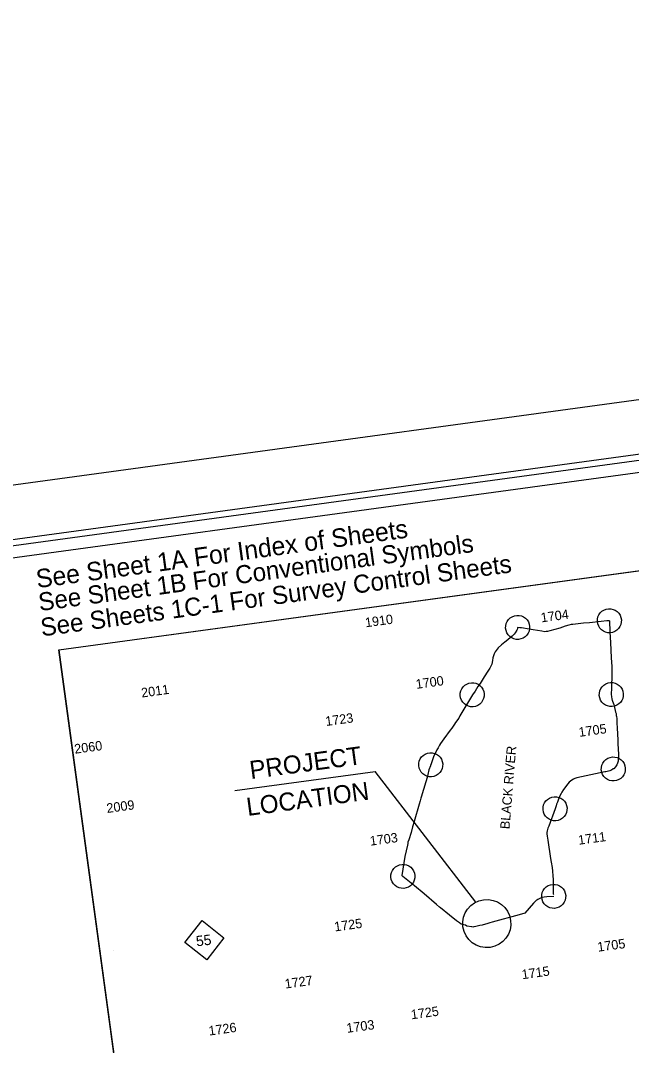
# Model space of a CAD drawing. Extents: x 2110583 to 2112764, y 580993 to 582575.
# Drawn here: x 2110891 to 2111195, y 582064 to 582575 of the extents above; entities that cross this region are included whole.
import ezdxf

# ---------------------------------------------------------------- set-up
doc = ezdxf.new("R2010")
doc.units = 0
for name, color, linetype in [('Default', 7, 'Continuous'), ('Prop DSN Text', 7, 'Continuous'), ('Scratch_Level_0', 7, 'Continuous'), ('Sheet Data Field CELL', 7, 'Continuous'), ('Sheet Plot Border Inside CELL', 7, 'Continuous'), ('Sheet Plot Border Outside CELL', 7, 'Continuous'), ('Sheet Title CELL', 7, 'Continuous')]:
    doc.layers.add(name, color=color, linetype=linetype)

msp = doc.modelspace()

# ---------------------------------------------------------------- linework, layer by layer
at = {"layer": 'Default'}
msp.add_line((2110936.95, 582111.14), (2110936.96, 582111.09), dxfattribs=at)
msp.add_lwpolyline([(2110972.71, 582114.94), (2110981.3, 582125.83), (2110992.19, 582117.24), (2110983.6, 582106.35)], close=True, dxfattribs=at)
at = {"layer": 'Prop DSN Text'}
for p in [(2110997.69, 582190.7), (2111117.86, 582135.05)]:
    msp.add_line(p, (2111067.61, 582200.13), dxfattribs=at)
for points in [[(2111138.67, 582272.05), (2111138.55, 582271.29), (2111138.34, 582270.7), (2111137.42, 582269.28), (2111136.98, 582268.68), (2111136.42, 582268.13), (2111135.98, 582267.64), (2111132.92, 582265.24)], [(2111184.43, 582275.37), (2111183.07, 582275.26), (2111180.3, 582275.01), (2111174.54, 582274.32), (2111171.51, 582274.1), (2111166.26, 582273.58), (2111165.4, 582273.46), (2111164.21, 582273.17), (2111162.44, 582272.64), (2111159.75, 582271.72), (2111154.74, 582270.39), (2111153.5, 582270.03), (2111152.96, 582269.95), (2111152.29, 582269.92), (2111150.77, 582270.13), (2111146.37, 582270.82), (2111144.44, 582271.2), (2111140.62, 582271.83), (2111139.73, 582271.91), (2111138.67, 582272.05)], [(2111184.43, 582275.37), (2111184.5, 582274.01), (2111184.61, 582271.1), (2111184.73, 582269.65), (2111185.05, 582264.6), (2111185.36, 582256.8), (2111185.68, 582252.63)], [(2111132.92, 582265.24), (2111132.27, 582264.74), (2111131.53, 582264.07), (2111130.63, 582263.35), (2111129.03, 582261.89), (2111128.43, 582261.27), (2111127.5, 582259.86), (2111126.99, 582258.84), (2111126.6, 582257.85), (2111126.29, 582256.84), (2111126.09, 582255.63), (2111125.72, 582253.77), (2111125.47, 582253.06), (2111124.81, 582251.8), (2111123.76, 582250.25), (2111122.01, 582247.38), (2111119.97, 582244.15), (2111118.89, 582242.5), (2111117.44, 582240.19), (2111116.24, 582238.4), (2111109.83, 582228.03), (2111109.34, 582226.8)], [(2111185.68, 582252.63), (2111185.62, 582249.88), (2111185.57, 582248.66), (2111185.43, 582241.91), (2111185.39, 582238.57), (2111185.44, 582237.62), (2111185.48, 582237.26), (2111185.6, 582236.64), (2111185.68, 582236.26), (2111185.77, 582235.98), (2111185.83, 582235.8), (2111186, 582235.26), (2111186.35, 582234.39), (2111186.57, 582233.62)], [(2111186.57, 582233.62), (2111186.78, 582232.92), (2111187.55, 582229.76), (2111187.73, 582229.15), (2111187.83, 582228.52), (2111187.89, 582228.16), (2111187.96, 582227.63), (2111188.06, 582226.6), (2111188.09, 582225.62), (2111188.19, 582224.43), (2111188.24, 582221.82)], [(2111109.34, 582226.8), (2111107.69, 582224.57), (2111107.26, 582223.86), (2111106.86, 582223.35), (2111105.86, 582221.88), (2111104.99, 582220.87), (2111101.85, 582216.46), (2111100.12, 582214.1), (2111099.64, 582213.32), (2111098.96, 582211.99), (2111098.34, 582211.07), (2111096.79, 582207.48), (2111095.32, 582203.53)], [(2111188.36, 582220.58), (2111188.39, 582220.29), (2111188.64, 582214.55), (2111188.83, 582211), (2111188.89, 582209.11), (2111188.91, 582206.93), (2111188.85, 582206.05), (2111188.74, 582205.28), (2111188.53, 582204.4), (2111188.16, 582203.54), (2111187.84, 582203), (2111187.46, 582202.44), (2111186.62, 582201.59), (2111186.39, 582201.46)], [(2111188.24, 582221.82), (2111188.24, 582221.68), (2111188.36, 582220.58)], [(2111095.32, 582203.53), (2111095.29, 582203.45), (2111095.14, 582202.95), (2111094.39, 582201.02), (2111093.82, 582198.73), (2111093.56, 582197.15)], [(2111182.09, 582199.98), (2111168.15, 582197.1), (2111167.19, 582196.75), (2111166.86, 582196.61), (2111166.51, 582196.41), (2111165.68, 582195.9), (2111165.08, 582195.44), (2111164.36, 582194.81), (2111163.73, 582194.08), (2111161.57, 582191.2), (2111160.72, 582189.9), (2111160.35, 582189.26), (2111159.35, 582187.31), (2111158.51, 582184.87), (2111158.12, 582183.86), (2111157.87, 582183.12)], [(2111186.39, 582201.46), (2111185.42, 582200.8), (2111185.04, 582200.61), (2111184.62, 582200.48), (2111182.59, 582200.08), (2111182.48, 582200.06), (2111182.09, 582199.98)], [(2111093.56, 582197.15), (2111092.94, 582195.05), (2111090.64, 582187.42), (2111090.46, 582186.82), (2111090.12, 582185.54), (2111089.61, 582183.91), (2111087.13, 582175.22)], [(2111157.47, 582182.04), (2111157.31, 582181.6), (2111154.16, 582172.96), (2111153.78, 582171.86), (2111153.4, 582170.59), (2111153.25, 582169.74), (2111153.28, 582168.76), (2111153.33, 582168.36), (2111153.42, 582167.96), (2111153.73, 582165.98), (2111155.13, 582156.86)], [(2111157.87, 582183.12), (2111157.83, 582183.02), (2111157.47, 582182.04)], [(2111087.13, 582175.22), (2111086.26, 582172.54), (2111085.49, 582169.83), (2111084.34, 582166.12), (2111083.97, 582164.89), (2111083.93, 582164.26), (2111083.77, 582163.53), (2111082.41, 582157.86), (2111080.89, 582148.26)], [(2111155.13, 582156.86), (2111155.47, 582155.02), (2111155.88, 582152.32), (2111156.12, 582150.43), (2111156.28, 582148.18), (2111156.31, 582146.37), (2111156.32, 582143.6)], [(2111120.99, 582123.63), (2111119.8, 582123.31), (2111117.9, 582122.9), (2111116.88, 582122.7), (2111116.32, 582122.63), (2111115.78, 582122.69), (2111113.41, 582123.14), (2111112.59, 582123.59), (2111111.79, 582123.75), (2111110.52, 582124.12), (2111109.63, 582124.75), (2111108.12, 582125.73), (2111104.61, 582128.56), (2111100.2, 582132.14), (2111099.65, 582132.56), (2111098.26, 582133.85), (2111092.01, 582139.26), (2111087.31, 582143.11), (2111081.43, 582147.88), (2111080.89, 582148.26)], [(2111156.32, 582143.6), (2111156.32, 582143.29), (2111156.36, 582140.63), (2111156.43, 582139.15), (2111156.48, 582138.92)], [(2111156.65, 582137.93), (2111153.23, 582137.69), (2111151.86, 582137.54), (2111151.13, 582137.39), (2111150.36, 582137.14), (2111149.79, 582136.93), (2111149.44, 582136.77), (2111148.7, 582136.35), (2111148.28, 582136.1), (2111147.89, 582135.79), (2111147.55, 582135.49), (2111147.22, 582135.16), (2111146.61, 582134.46), (2111142.18, 582129.58)], [(2111142.18, 582129.58), (2111139.36, 582128.72), (2111125.97, 582125.05)], [(2111125.97, 582125.05), (2111124.83, 582124.69), (2111124.34, 582124.54), (2111123.86, 582124.42), (2111120.99, 582123.63)]]:
    msp.add_lwpolyline(points, dxfattribs=at)
for centre, major_axis in [((2111184.43, 582275.37), (-1.61, 5.78)), ((2111138.67, 582272.05), (-1.61, 5.78)), ((2111116, 582238.47), (-1.61, 5.78)), ((2111185.39, 582238.57), (-1.61, 5.78)), ((2111095.32, 582203.53), (-1.61, 5.78)), ((2111186.39, 582201.46), (-1.61, 5.78)), ((2111157.31, 582181.6), (-1.61, 5.78)), ((2111081.43, 582147.88), (-1.61, 5.78)), ((2111156.65, 582137.93), (-1.61, 5.78)), ((2111123.29, 582124.34), (1.62, -11.9))]:
    msp.add_ellipse(centre, major_axis=major_axis, ratio=0.999692, dxfattribs=at)
at = {"layer": 'Scratch_Level_0'}
msp.add_lwpolyline([(2110909.81, 582260.89), (2111242.78, 582306.33), (2111281.74, 582020.84), (2110948.77, 581975.4)], close=True, dxfattribs=at)
at = {"layer": 'Sheet Plot Border Inside CELL'}
msp.add_lwpolyline([(2110773, 581021.72), (2112754.79, 581292.17), (2112583.51, 582547.28), (2110601.71, 582276.83)], close=True, dxfattribs=at)
at = {"layer": 'Sheet Plot Border Outside CELL'}
msp.add_lwpolyline([(2112585.22, 582574.72), (2110582.61, 582301.43), (2110761.18, 580992.92), (2112763.78, 581266.21)], close=True, dxfattribs=at)
at = {"layer": 'Sheet Title CELL'}
for q in [(2111242.78, 582306.33), (2110956.89, 581915.92)]:
    msp.add_line((2110909.81, 582260.89), q, dxfattribs=at)
for points in [[(2112557.18, 582540.6), (2110797.14, 582300.43)], [(2112552.03, 582533.84), (2110863.39, 582303.39)]]:
    msp.add_lwpolyline(points, dxfattribs=at)

# ---------------------------------------------------------------- texts
at = {"layer": 'Default'}
for s, height, rotation, p in [('1910', 4.705, 7.771, (2111062.9, 582272.08)), ('1704', 4.705, 7.771, (2111150.53, 582274.54)), ('1700', 4.705, 7.771, (2111088.18, 582241.39)), ('2011', 4.705, 7.771, (2110951.26, 582237.06)), ('1723', 4.705, 7.771, (2111043.1, 582222.87)), ('1705', 4.705, 7.771, (2111169.42, 582217.45)), ('2060', 4.705, 7.771, (2110917.9, 582209.03)), ('BLACK RIVER', 4.7046, 85.2808, (2111134.59, 582171.29)), ('2009', 4.705, 7.771, (2110933.96, 582179.49)), ('1703', 4.705, 7.771, (2111065.28, 582163.16)), ('1711', 4.705, 7.771, (2111169.13, 582163.63)), ('1725', 4.705, 7.771, (2111047.54, 582120.4)), ('55', 5.153, 6.7335, (2110978.57, 582112.97)), ('1705', 4.705, 7.771, (2111178.77, 582110.29)), ('1705', 4.705, 7.771, (2111178.77, 582110.29)), ('1715', 4.705, 7.771, (2111141, 582096.58)), ('1727', 4.705, 7.771, (2111022.84, 582091.93)), ('1725', 4.705, 7.771, (2111085.75, 582076.58)), ('1726', 4.705, 7.771, (2110984.87, 582068.48)), ('1703', 4.705, 7.771, (2111053.63, 582069.83))]:
    msp.add_text(s, height=height, rotation=rotation, dxfattribs=at).set_placement(p)
at = {"layer": 'Sheet Data Field CELL'}
for s, p in [('PROJECT', (2111005.62, 582196.38)), ('LOCATION', (2111004.04, 582178))]:
    msp.add_text(s, height=9.004, rotation=7.686, dxfattribs=at).set_placement(p)
at = {"layer": 'Sheet Title CELL'}
for s, height, p in [('See Sheet 1A For Index of Sheets', 9.2119, (2110899.13, 582291.62)), ('See Sheet 1B For Conventional Symbols', 9.0044, (2110900.28, 582280.16)), ('See Sheets 1C-1 For Survey Control Sheets', 9.0044, (2110901.37, 582267.54))]:
    msp.add_text(s, height=height, rotation=7.771, dxfattribs=at).set_placement(p)

doc.saveas('drawing.dxf')
